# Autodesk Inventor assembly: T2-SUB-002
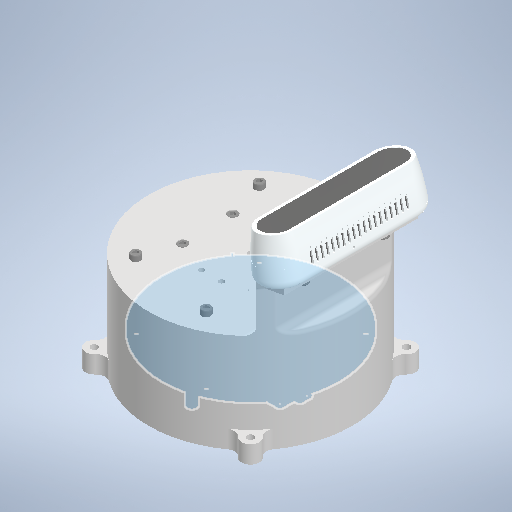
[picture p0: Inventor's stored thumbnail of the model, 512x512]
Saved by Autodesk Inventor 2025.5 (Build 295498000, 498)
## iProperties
Created: 2026-10
Part Number: T2-SUB-002
Document SubType Name: Assembly
Designer: Luis MuÃ±oz
Project: TESIS 2 - Plataforma mecatrÃ³nica preventiva desacoplada
Description: Módulo de electrónica y percepción RGB-D
Author: Luis M
Title: MÃ³dulo de electrÃ³nica y percepciÃ³n RGB-D
Revision Number: 00
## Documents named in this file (11)
- C:\Users\Luis M\Desktop\TESIS\CAD_TESIS_PRUEBA_MIGRACION\02_ELECTRONICA\IAM\MODULO_ELECTRONICA_PERCEPCION_RGBD.iam
- C:\Users\Luis M\Desktop\TESIS\CAD_TESIS_PRUEBA_MIGRACION\02_ELECTRONICA\CARCASA\CARCASA_ELECTRONICA_GRIPPER.ipt
- C:\Users\Luis M\Desktop\TESIS\CAD_TESIS_PRUEBA_MIGRACION\05_BIBLIOTECA_COMERCIAL\FIJACIONES\SEPARADOR_HH_M3X10_LATON.ipt
- C:\Users\Luis M\Desktop\TESIS\CAD_TESIS_PRUEBA_MIGRACION\05_BIBLIOTECA_COMERCIAL\FIJACIONES\TORNILLO_HEX_INTERIOR_M3X8.ipt
- C:\Users\Luis M\Desktop\TESIS\CAD_TESIS_PRUEBA_MIGRACION\05_BIBLIOTECA_COMERCIAL\CAMARA\INTEL_REALSENSE_D435I.ipt
- C:\Users\Luis M\Desktop\TESIS\CAD_TESIS_PRUEBA_MIGRACION\05_BIBLIOTECA_COMERCIAL\FIJACIONES\INSERTO_ROSCADO_M3_D5_L5.ipt
- C:\Users\Luis M\Desktop\TESIS\CAD_TESIS_PRUEBA_MIGRACION\02_ELECTRONICA\PCB\ENSAMBLE_ORIGINAL\FEETECH_URT2.ipt
- C:\Users\Luis M\Desktop\TESIS\CAD_TESIS_PRUEBA_MIGRACION\02_ELECTRONICA\PCB\ENSAMBLE_ORIGINAL\Separador laton H-H M3x20mm.ipt
- C:\Users\Luis M\Desktop\TESIS\CAD_TESIS_PRUEBA_MIGRACION\02_ELECTRONICA\PCB\ENSAMBLE_ORIGINAL\Separador laton H-M M3x10x6mm.ipt
- C:\Users\Luis M\Desktop\TESIS\CAD_TESIS_PRUEBA_MIGRACION\01_GRIPPER\IPT_PROPIAS\TAPA_GRIPPER.ipt
- C:\Users\Luis M\Desktop\TESIS\CAD_TESIS_PRUEBA_MIGRACION\02_ELECTRONICA\PCB\ENSAMBLE_ORIGINAL\PCB_ENSAMBLE.iam
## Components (31 placed, 10 different names)
1. CARCASA_GRIPPER:1
2. SEPARADOR_HH_M3X10_LATON:1 — Nivelación:1, Nivelación:2, Coincidencia:24
3. SEPARADOR_HH_M3X10_LATON:2 — Nivelación:2, Nivelación:3, Coincidencia:5, Coincidencia:23, Coincidencia:27
4. SEPARADOR_HH_M3X10_LATON:3 — Nivelación:1, Coincidencia:25, Coincidencia:28, Coincidencia:29
5. SEPARADOR_HH_M3X10_LATON:4 — Nivelación:3, Coincidencia:26
6. TORNILLO_HEX_INTERIOR_M3X8:1 — Nivelación:6, Coincidencia:31
7. TORNILLO_HEX_INTERIOR_M3X8:2 — Nivelación:4, Coincidencia:33
8. TORNILLO_HEX_INTERIOR_M3X8:3 — Nivelación:4, Nivelación:5, Coincidencia:30, Coincidencia:32
9. TORNILLO_HEX_INTERIOR_M3X8:4 — Nivelación:5, Nivelación:6, Coincidencia:34
10. INTEL_REALSENSE_D435I:1 — Coincidencia:13, Coincidencia:14, Coincidencia:15
11. Insert M3 D5 L5mm:1 — Nivelación:22, Nivelación:23, Coincidencia:61, Coincidencia:64
12. Insert M3 D5 L5mm:2 — Nivelación:23, Nivelación:24, Coincidencia:60
13. Insert M3 D5 L5mm:3 — Nivelación:21, Coincidencia:62, Coincidencia:65
14. Insert M3 D5 L5mm:4 — Nivelación:21, Nivelación:22, Coincidencia:63
15. TORNILLO_HEX_INTERIOR_M3X8:5 — Nivelación:11, Coincidencia:21
16. TORNILLO_HEX_INTERIOR_M3X8:6 — Nivelación:11, Coincidencia:20, Coincidencia:22
17. FEETECH_URT2:1 — Coincidencia:27, Coincidencia:28, Coincidencia:29
18. Separador laton H-H M3x20mm:1 — Nivelación:12, Coincidencia:48
19. Separador laton H-H M3x20mm:2 — Nivelación:13, Nivelación:14, Coincidencia:44, Coincidencia:46
20. Separador laton H-H M3x20mm:3 — Nivelación:12, Nivelación:13, Coincidencia:45
21. Separador laton H-H M3x20mm:4 — Nivelación:14, Coincidencia:43, Coincidencia:47
22. Separador laton H-M M3x10x6mm:1 — Nivelación:15, Coincidencia:45, Coincidencia:52
23. Separador laton H-M M3x10x6mm:2 — Nivelación:15, Nivelación:16, Coincidencia:47, Coincidencia:51
24. Separador laton H-M M3x10x6mm:3 — Nivelación:16, Nivelación:17, Coincidencia:48, Coincidencia:50, Coincidencia:68
25. Separador laton H-M M3x10x6mm:4 — Nivelación:17, Coincidencia:44, Coincidencia:46, Coincidencia:49, Coincidencia:67
26. TORNILLO_HEX_INTERIOR_M3X8:7 — Nivelación:18, Coincidencia:57
27. TORNILLO_HEX_INTERIOR_M3X8:8 — Nivelación:18, Nivelación:19, Coincidencia:55, Coincidencia:56
28. TORNILLO_HEX_INTERIOR_M3X8:9 — Nivelación:19, Nivelación:20, Coincidencia:59
29. TORNILLO_HEX_INTERIOR_M3X8:10 — Nivelación:20, Coincidencia:58
30. TAPA_GRIPPER:1 — Coincidencia:64, Coincidencia:65, Coincidencia:66
31. PCB_ENSAMBLE:1 [sub-assembly] — Coincidencia:67, Coincidencia:68
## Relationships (63: Mate 43, Flush 20)
- Nivelación:1 [Flush]: SEPARADOR_HH_M3X10_LATON:1 ↔ SEPARADOR_HH_M3X10_LATON:3
- Nivelación:2 [Flush]: SEPARADOR_HH_M3X10_LATON:1 ↔ SEPARADOR_HH_M3X10_LATON:2
- Nivelación:3 [Flush]: SEPARADOR_HH_M3X10_LATON:2 ↔ SEPARADOR_HH_M3X10_LATON:4
- Coincidencia:5 [Mate]: SEPARADOR_HH_M3X10_LATON:2
- Nivelación:4 [Flush]: TORNILLO_HEX_INTERIOR_M3X8:2 ↔ TORNILLO_HEX_INTERIOR_M3X8:3
- Nivelación:5 [Flush]: TORNILLO_HEX_INTERIOR_M3X8:3 ↔ TORNILLO_HEX_INTERIOR_M3X8:4
- Nivelación:6 [Flush]: TORNILLO_HEX_INTERIOR_M3X8:1 ↔ TORNILLO_HEX_INTERIOR_M3X8:4
- Coincidencia:13 [Mate]: INTEL_REALSENSE_D435I:1
- Coincidencia:14 [Mate]: INTEL_REALSENSE_D435I:1
- Coincidencia:15 [Mate]: INTEL_REALSENSE_D435I:1
- Nivelación:11 [Flush]: TORNILLO_HEX_INTERIOR_M3X8:5 ↔ TORNILLO_HEX_INTERIOR_M3X8:6
- Coincidencia:20 [Mate]: TORNILLO_HEX_INTERIOR_M3X8:6
- Coincidencia:21 [Mate]: TORNILLO_HEX_INTERIOR_M3X8:5
- Coincidencia:22 [Mate]: TORNILLO_HEX_INTERIOR_M3X8:6
- Coincidencia:23 [Mate]: SEPARADOR_HH_M3X10_LATON:2
- Coincidencia:24 [Mate]: SEPARADOR_HH_M3X10_LATON:1
- Coincidencia:25 [Mate]: SEPARADOR_HH_M3X10_LATON:3
- Coincidencia:26 [Mate]: SEPARADOR_HH_M3X10_LATON:4
- Coincidencia:27 [Mate]: SEPARADOR_HH_M3X10_LATON:2 ↔ FEETECH_URT2:1
- Coincidencia:28 [Mate]: SEPARADOR_HH_M3X10_LATON:3 ↔ FEETECH_URT2:1
- Coincidencia:29 [Mate]: SEPARADOR_HH_M3X10_LATON:3 ↔ FEETECH_URT2:1
- Coincidencia:30 [Mate]: TORNILLO_HEX_INTERIOR_M3X8:3
- Coincidencia:31 [Mate]: TORNILLO_HEX_INTERIOR_M3X8:1
- Coincidencia:32 [Mate]: TORNILLO_HEX_INTERIOR_M3X8:3
- Coincidencia:33 [Mate]: TORNILLO_HEX_INTERIOR_M3X8:2
- Coincidencia:34 [Mate]: TORNILLO_HEX_INTERIOR_M3X8:4
- Nivelación:12 [Flush]: Separador laton H-H M3x20mm:1 ↔ Separador laton H-H M3x20mm:3
- Nivelación:13 [Flush]: Separador laton H-H M3x20mm:2 ↔ Separador laton H-H M3x20mm:3
- Nivelación:14 [Flush]: Separador laton H-H M3x20mm:2 ↔ Separador laton H-H M3x20mm:4
- Coincidencia:43 [Mate]: Separador laton H-H M3x20mm:4
- Nivelación:15 [Flush]: Separador laton H-M M3x10x6mm:1 ↔ Separador laton H-M M3x10x6mm:2
- Nivelación:16 [Flush]: Separador laton H-M M3x10x6mm:2 ↔ Separador laton H-M M3x10x6mm:3
- Nivelación:17 [Flush]: Separador laton H-M M3x10x6mm:3 ↔ Separador laton H-M M3x10x6mm:4
- Coincidencia:44 [Mate]: Separador laton H-H M3x20mm:2 ↔ Separador laton H-M M3x10x6mm:4
- Coincidencia:45 [Mate]: Separador laton H-H M3x20mm:3 ↔ Separador laton H-M M3x10x6mm:1
- Coincidencia:46 [Mate]: Separador laton H-H M3x20mm:2 ↔ Separador laton H-M M3x10x6mm:4
- Coincidencia:47 [Mate]: Separador laton H-H M3x20mm:4 ↔ Separador laton H-M M3x10x6mm:2
- Coincidencia:48 [Mate]: Separador laton H-H M3x20mm:1 ↔ Separador laton H-M M3x10x6mm:3
- Coincidencia:49 [Mate]: Separador laton H-M M3x10x6mm:4
- Coincidencia:50 [Mate]: Separador laton H-M M3x10x6mm:3
- Coincidencia:51 [Mate]: Separador laton H-M M3x10x6mm:2
- Coincidencia:52 [Mate]: Separador laton H-M M3x10x6mm:1
- Nivelación:18 [Flush]: TORNILLO_HEX_INTERIOR_M3X8:7 ↔ TORNILLO_HEX_INTERIOR_M3X8:8
- Nivelación:19 [Flush]: TORNILLO_HEX_INTERIOR_M3X8:8 ↔ TORNILLO_HEX_INTERIOR_M3X8:9
- Nivelación:20 [Flush]: TORNILLO_HEX_INTERIOR_M3X8:9 ↔ TORNILLO_HEX_INTERIOR_M3X8:10
- Coincidencia:55 [Mate]: TORNILLO_HEX_INTERIOR_M3X8:8
- Coincidencia:56 [Mate]: TORNILLO_HEX_INTERIOR_M3X8:8
- Coincidencia:57 [Mate]: TORNILLO_HEX_INTERIOR_M3X8:7
- Coincidencia:58 [Mate]: TORNILLO_HEX_INTERIOR_M3X8:10
- Coincidencia:59 [Mate]: TORNILLO_HEX_INTERIOR_M3X8:9
- Nivelación:21 [Flush]: Insert M3 D5 L5mm:3 ↔ Insert M3 D5 L5mm:4
- Nivelación:22 [Flush]: Insert M3 D5 L5mm:1 ↔ Insert M3 D5 L5mm:4
- Nivelación:23 [Flush]: Insert M3 D5 L5mm:1 ↔ Insert M3 D5 L5mm:2
- Nivelación:24 [Flush]: Insert M3 D5 L5mm:2
- Coincidencia:60 [Mate]: Insert M3 D5 L5mm:2
- Coincidencia:61 [Mate]: Insert M3 D5 L5mm:1
- Coincidencia:62 [Mate]: Insert M3 D5 L5mm:3
- Coincidencia:63 [Mate]: Insert M3 D5 L5mm:4
- Coincidencia:64 [Mate]: Insert M3 D5 L5mm:1 ↔ TAPA_GRIPPER:1
- Coincidencia:65 [Mate]: Insert M3 D5 L5mm:3 ↔ TAPA_GRIPPER:1
- Coincidencia:66 [Mate]: TAPA_GRIPPER:1
- Coincidencia:67 [Mate]: Separador laton H-M M3x10x6mm:4 ↔ PCB_ENSAMBLE:1
- Coincidencia:68 [Mate]: Separador laton H-M M3x10x6mm:3 ↔ PCB_ENSAMBLE:1
